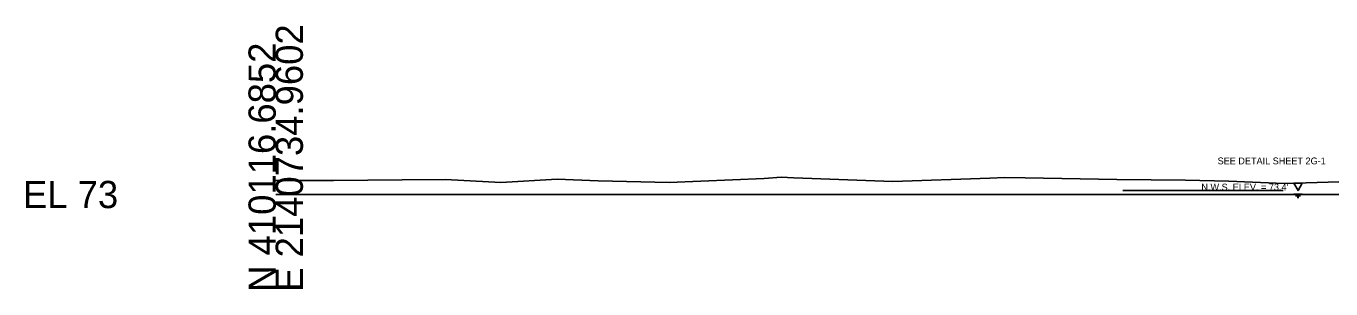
# Model space of a CAD drawing. Extents: x -14026 to 1303, y -10 to 9533.
# Drawn here: x -25.7 to 108.6, y 3990.3 to 4017.3 of the extents above; entities that cross this region are included whole.
import ezdxf

# ---------------------------------------------------------------- set-up
doc = ezdxf.new("R2010")
doc.units = 0
for name, color, linetype in [('Default', 7, 'Continuous'), ('Exist Cross Section Cell', 7, 'Continuous'), ('Exist XS Ground Line', 7, 'Continuous'), ('Old_Level_10', 7, 'Continuous'), ('Prop XS Side Slope Text', 7, 'Continuous'), ('Scratch_Level_1', 7, 'Continuous')]:
    doc.layers.add(name, color=color, linetype=linetype)

msp = doc.modelspace()

# ---------------------------------------------------------------- linework, layer by layer
at = {"layer": 'Exist Cross Section Cell'}
msp.add_line((0, 4000), (150, 4000), dxfattribs=at)
at = {"layer": 'Exist XS Ground Line'}
msp.add_lwpolyline([(0, 4001.43), (5.94, 4001.43), (13.02, 4001.49), (17.46, 4001.53), (23.17, 4001.22), (28.98, 4001.56), (33.18, 4001.42), (40.49, 4001.22), (50.26, 4001.65), (52.01, 4001.79), (53.33, 4001.72), (63.53, 4001.34), (73.49, 4001.68), (75.05, 4001.73), (77.14, 4001.71), (86.57, 4001.53), (93.64, 4001.47), (98.09, 4001.38), (103.8, 4001.14), (113.96, 4001.43)], dxfattribs=at)
at = {"layer": 'Prop XS Side Slope Text'}
for p, q in [((104.79, 4000.05), (105.66, 4000.05)), ((104.96, 3999.87), (105.49, 3999.87)), ((105.14, 3999.7), (105.31, 3999.7))]:
    msp.add_line(p, q, dxfattribs=at)
msp.add_lwpolyline([(104.8, 4001.16), (105.67, 4001.16), (105.24, 4000.4)], close=True, dxfattribs=at)
at = {"layer": 'Scratch_Level_1'}
msp.add_line((87.21, 4000.4), (103.69, 4000.4), dxfattribs=at)

# ---------------------------------------------------------------- texts
at = {"layer": 'Default'}
msp.add_text('-', height=0.0001, dxfattribs=at).set_placement((0, 4000))
at = {"layer": 'Exist Cross Section Cell'}
for s, p in [('E 2140734.9602', (2.8, 3990)), ('N 410116.6852', (0, 3990))]:
    msp.add_text(s, height=2.8, rotation=90, dxfattribs=at).set_placement(p)
msp.add_text('EL 73', height=2.8, dxfattribs=at).set_placement((-26, 3998.6))
at = {"layer": 'Old_Level_10'}
msp.add_text('SEE DETAIL SHEET 2G-1', height=0.7, dxfattribs=at).set_placement((96.95, 4003.1))
at = {"layer": 'Prop XS Side Slope Text'}
msp.add_text("N.W.S. ELEV. = 73.4'", height=0.7, dxfattribs=at).set_placement((95.28, 4000.41))

doc.saveas('drawing.dxf')
